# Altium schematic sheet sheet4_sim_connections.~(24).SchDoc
size A3; Author: Mauri Shadi; CompanyName: BFH; DrawnBy: Mauri Shadi; SheetNumber: 1; SheetTotal: 2
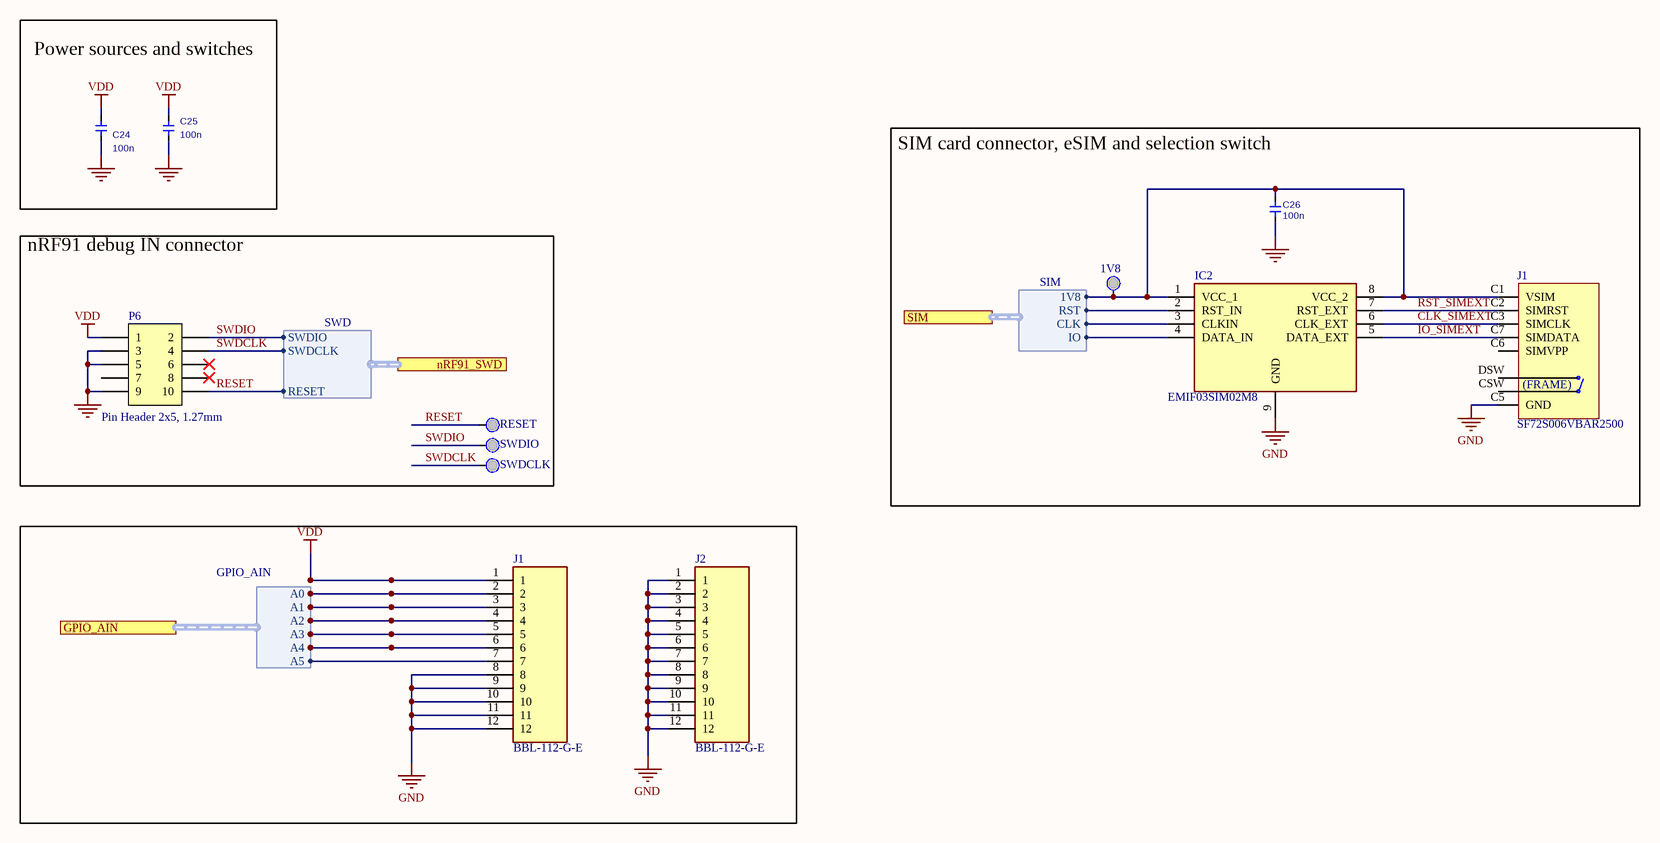
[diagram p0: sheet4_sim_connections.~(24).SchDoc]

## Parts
(Parts that share a designator on the sheet are numbered #1, #2 ... from top to bottom, then left to right.)
1V8  TESTPOINT_Black_Small  [Testpoint_Black_Small]  (value not drawn)
C24  100n  [0603(1608)C]
C25  100n  [0603(1608)C]
C26  100n  [0603(1608)C]
IC2  EMIF03SIM02M8  [SON40P150X170X60-9N-D]
J1#1  SF72S006VBAR2500  [SF72S006VBAR2500]
J1#2  BBL-112-G-E  [BBL-112-Y-X]
J2  BBL-112-G-E  [BBL-112-Y-X]
P6  Pin Header 2x5, 1.27mm  [HDR_2x5-SMD-1.27mm-K]
RESET  TESTPOINT_Black_Small  [Testpoint_Black_Small]  (value not drawn)
SWDCLK  TESTPOINT_Black_Small  [Testpoint_Black_Small]  (value not drawn)
SWDIO  TESTPOINT_Black_Small  [Testpoint_Black_Small]  (value not drawn)

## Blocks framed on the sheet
Power sources and switches: C24 C25
SIM card connector, eSIM and selection switch: 1V8 C26 IC2 J1#1
nRF91 debug IN connector: P6 RESET SWDCLK SWDIO

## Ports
GPIO_AIN (harness GPIO_AIN, see sheet2_nRF9160[7C]), nRF91_SWD (harness SWD, see sheet2_nRF9160[7D]), SIM (harness SIM, see sheet2_nRF9160[7C])

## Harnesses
SWD: SWDIO, SWDCLK, RESET
GPIO_AIN: A0, A1, A2, A3, A4, A5
SIM: CLK, IO, 1V8, RST

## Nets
GND: C24.2 C25.1 C26.1 IC2.9(GND) J1#1.0(GND) J1#1.C5(GND) J1#2.8 J1#2.9 J1#2.10 J1#2.11 J1#2.12 J2.1 J2.2 J2.3 J2.4 J2.5 J2.6 J2.7 J2.8 J2.9 J2.10 J2.11 J2.12 P6.3 P6.5 P6.9
VDD: C24.1 C25.2 J1#2.1 P6.1
CLK_SIMEXT: IC2.6(CLK_EXT) J1#1.C3(SIMCLK)
IO_SIMEXT: IC2.5(DATA_EXT) J1#1.C7(SIMDATA)
RESET: P6.10 RESET.1 ; port nRF91_SWD.RESET
RST_SIMEXT: IC2.7(RST_EXT) J1#1.C2(SIMRST)
SWDCLK: P6.4 SWDCLK.1 ; port nRF91_SWD.SWDCLK
SWDIO: P6.2 SWDIO.1 ; port nRF91_SWD.SWDIO
Net1V8_1: 1V8.1 C26.2 IC2.1(VCC_1) IC2.8(VCC_2) J1#1.C1(VSIM) ; port SIM.1V8
NetIC2_2: IC2.2(RST_IN) ; port SIM.RST
NetIC2_3: IC2.3(CLKIN) ; port SIM.CLK
NetIC2_4: IC2.4(DATA_IN) ; port SIM.IO
NetJ1#2_2: J1#2.2 ; port GPIO_AIN.A0
NetJ1#2_3: J1#2.3 ; port GPIO_AIN.A1
NetJ1#2_4: J1#2.4 ; port GPIO_AIN.A2
NetJ1#2_5: J1#2.5 ; port GPIO_AIN.A3
NetJ1#2_6: J1#2.6 ; port GPIO_AIN.A4
NetJ1#2_7: J1#2.7 ; port GPIO_AIN.A5

Not connected (* = marked no-connect by the designer): J1#1 C6(SIMVPP) CSW DSW; P6 6* 7 8*

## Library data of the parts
1V8 RESET SWDCLK SWDIO = TESTPOINT_Black_Small: PCB Test Point, Black, Through Hole Mount, 3.2 mm, Phosphor Bronze; Manufacturer: MULTICOMP; Manufacturer P/N: TEST-1(R)
C24 C25 = C0603_5_100n_25V: Cer Chip Capacitor / 100n/ +-5%/ 25V; Manufacturer Part Number: CC0603KRX7R8BB104; Manufacturer 1: Yageo; Special Value 1: +-5%; Capacitance: 100nF; Tolerance: 10%; Dielectric: X7R
C26 = C0603_5_100n_25V: Cer Chip Capacitor / 100n/ +-5%/ 25V; Manufacturer 1: Yageo; Manufacturer Part Number: CC0603KRX7R8BB104; Special Value 1: +-5%; Capacitance: 100nF; Tolerance: 10%; Dielectric: X7R
IC2 = EMIF03SIM02M8: Integrated Circuit; Manufacturer_Name: STMicroelectronics
J1#1 = SF72S006VBAR2500: n 8 (6 + 2) Position Card Connector NANO SIM Surface Mount, Right Angle Gold; Manufacturer: JAE Electronics; Part number IPS: 00000009956; Note: N.A.; Pad Count: 8
J1#2 J2 = BBL-112-G-E: Connector; Manufacturer_Name: SAMTEC
P6 = Pin Header 2x5 SMD, 1.27mm, KS: Pin Header 2x5, 1.27mm (50mil), SMD, Keying Shroud; Manufacturer: W-CON; Manufacturer Part Number: 3132-10MS0BK00R1; Part number IPS: 00000009968; Note: N.A.; Artikkelnr Noca: 55010009; Pad Count: 10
